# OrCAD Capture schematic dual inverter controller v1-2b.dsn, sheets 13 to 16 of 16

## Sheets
13 Temperature Sense: size A; title: Controller
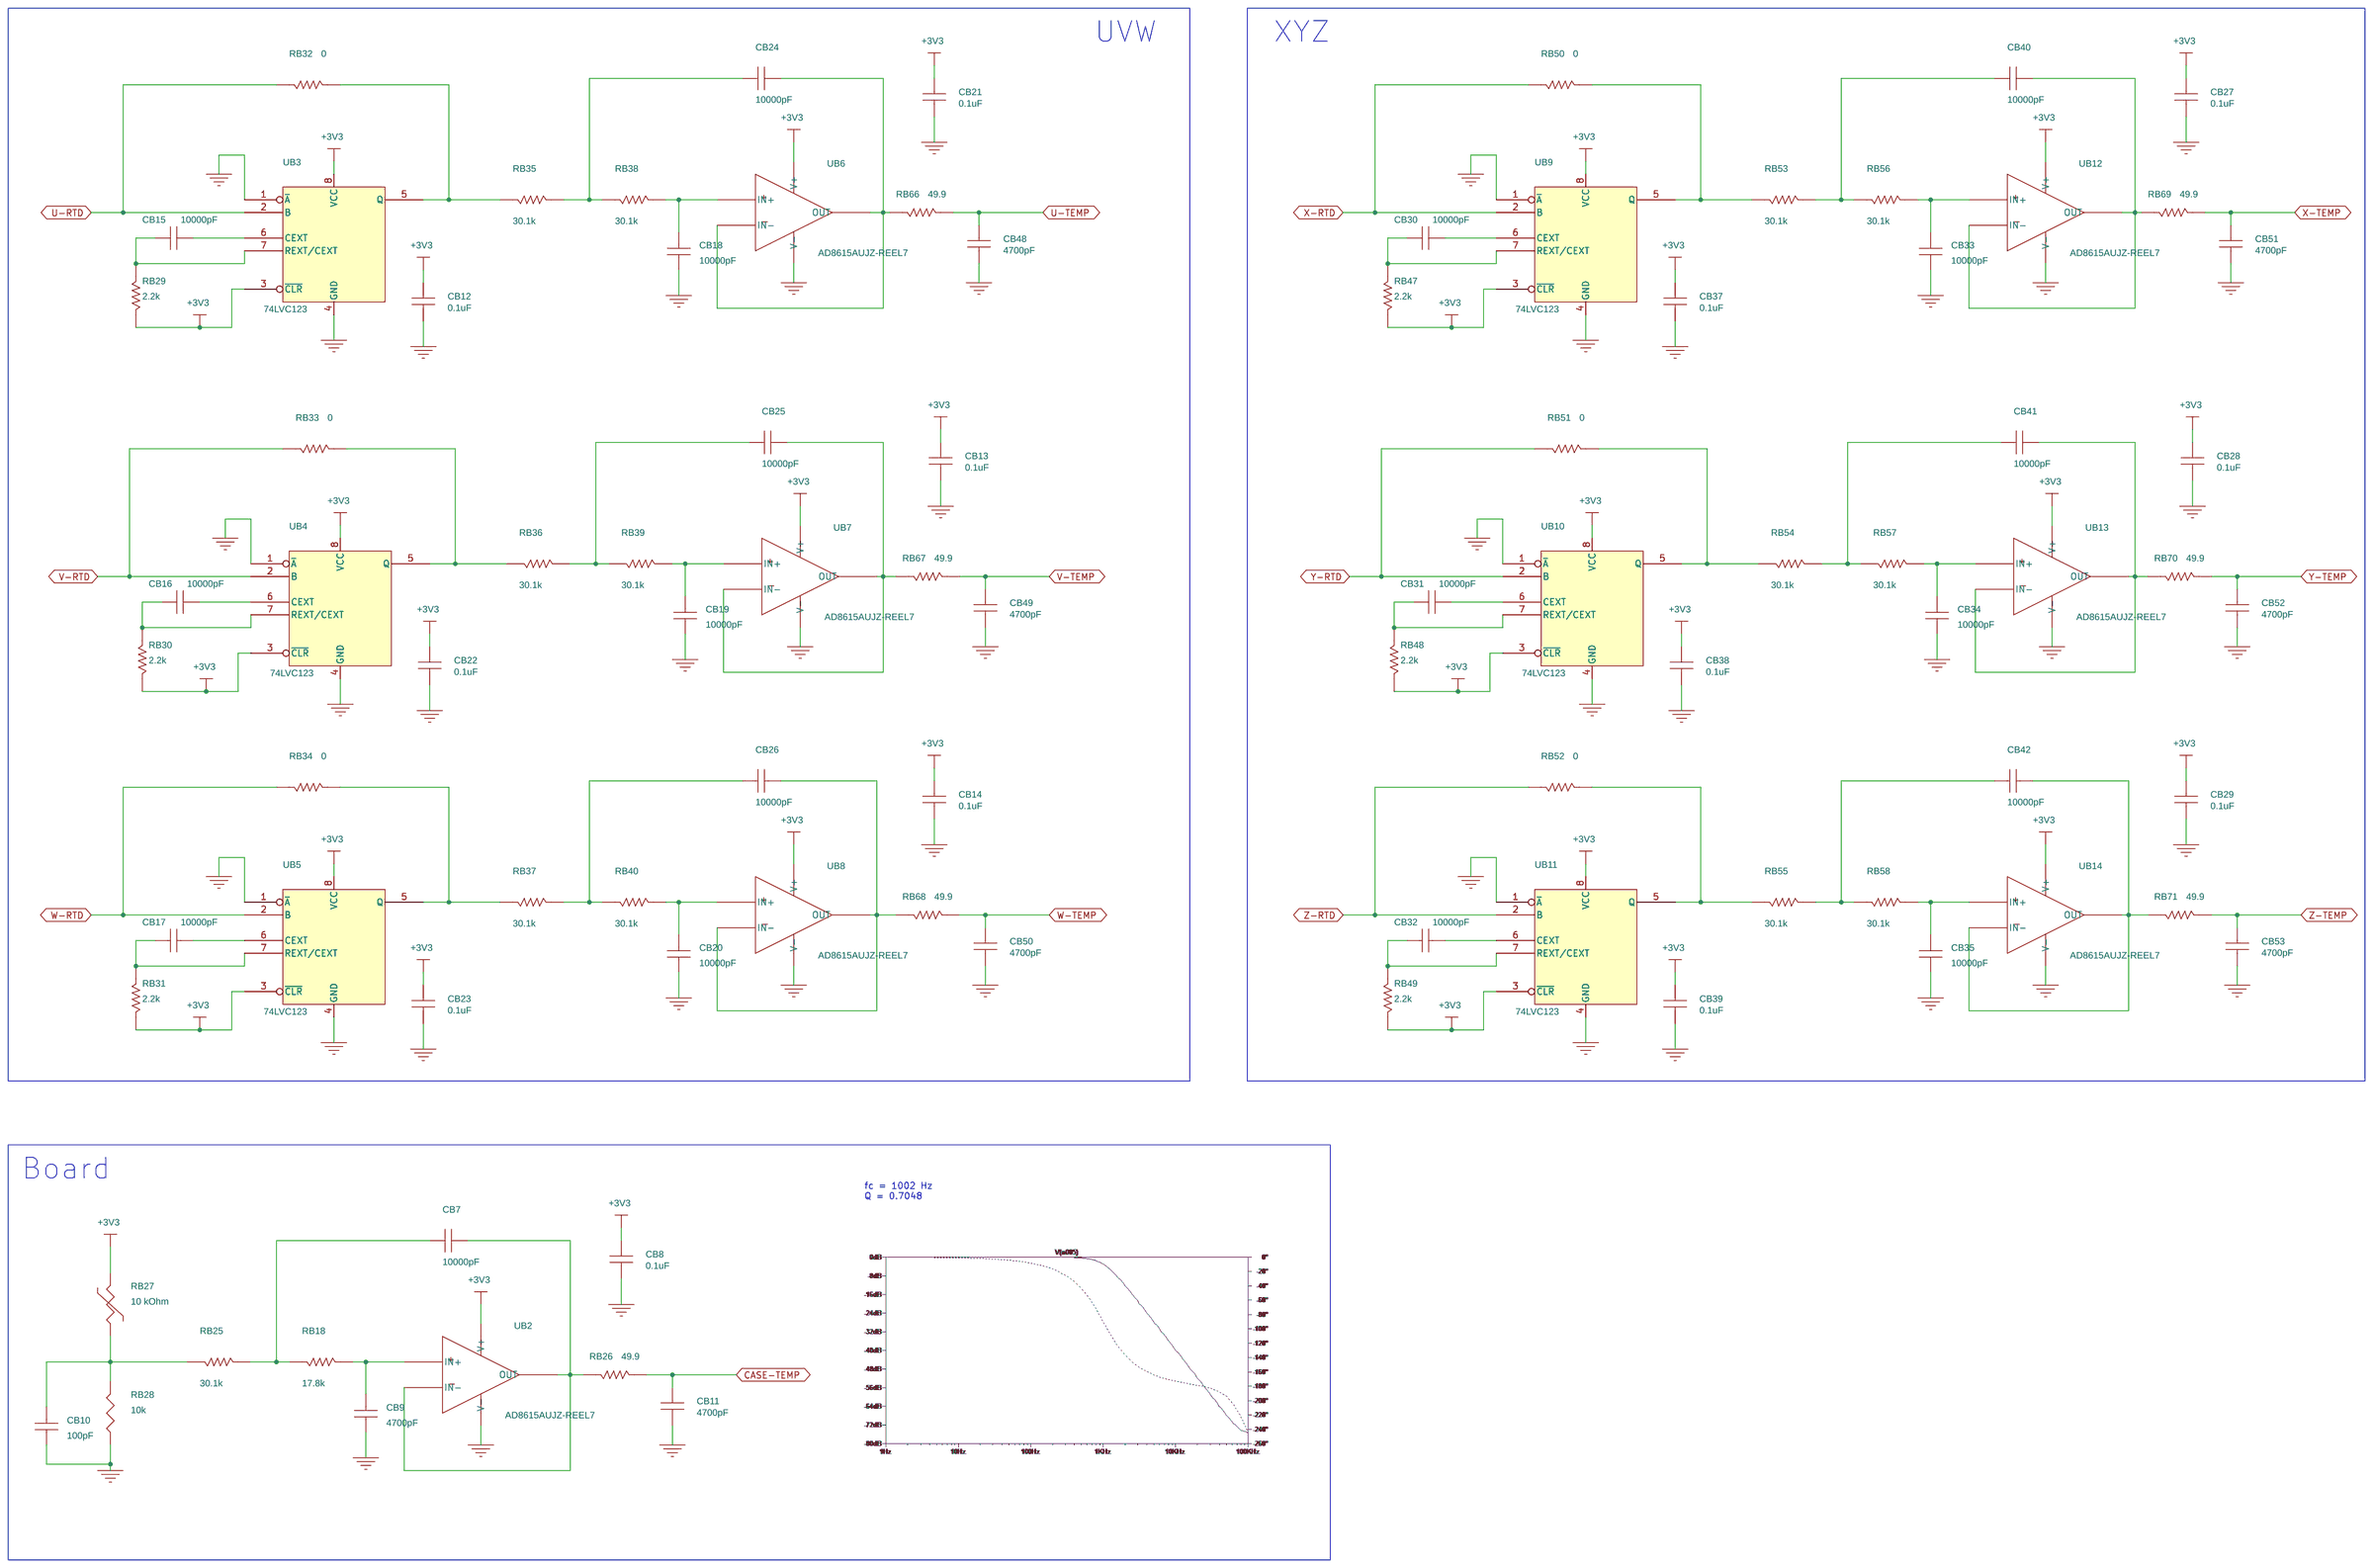
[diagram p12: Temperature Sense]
14 Voltage Sense UVW: size A; title: Controller
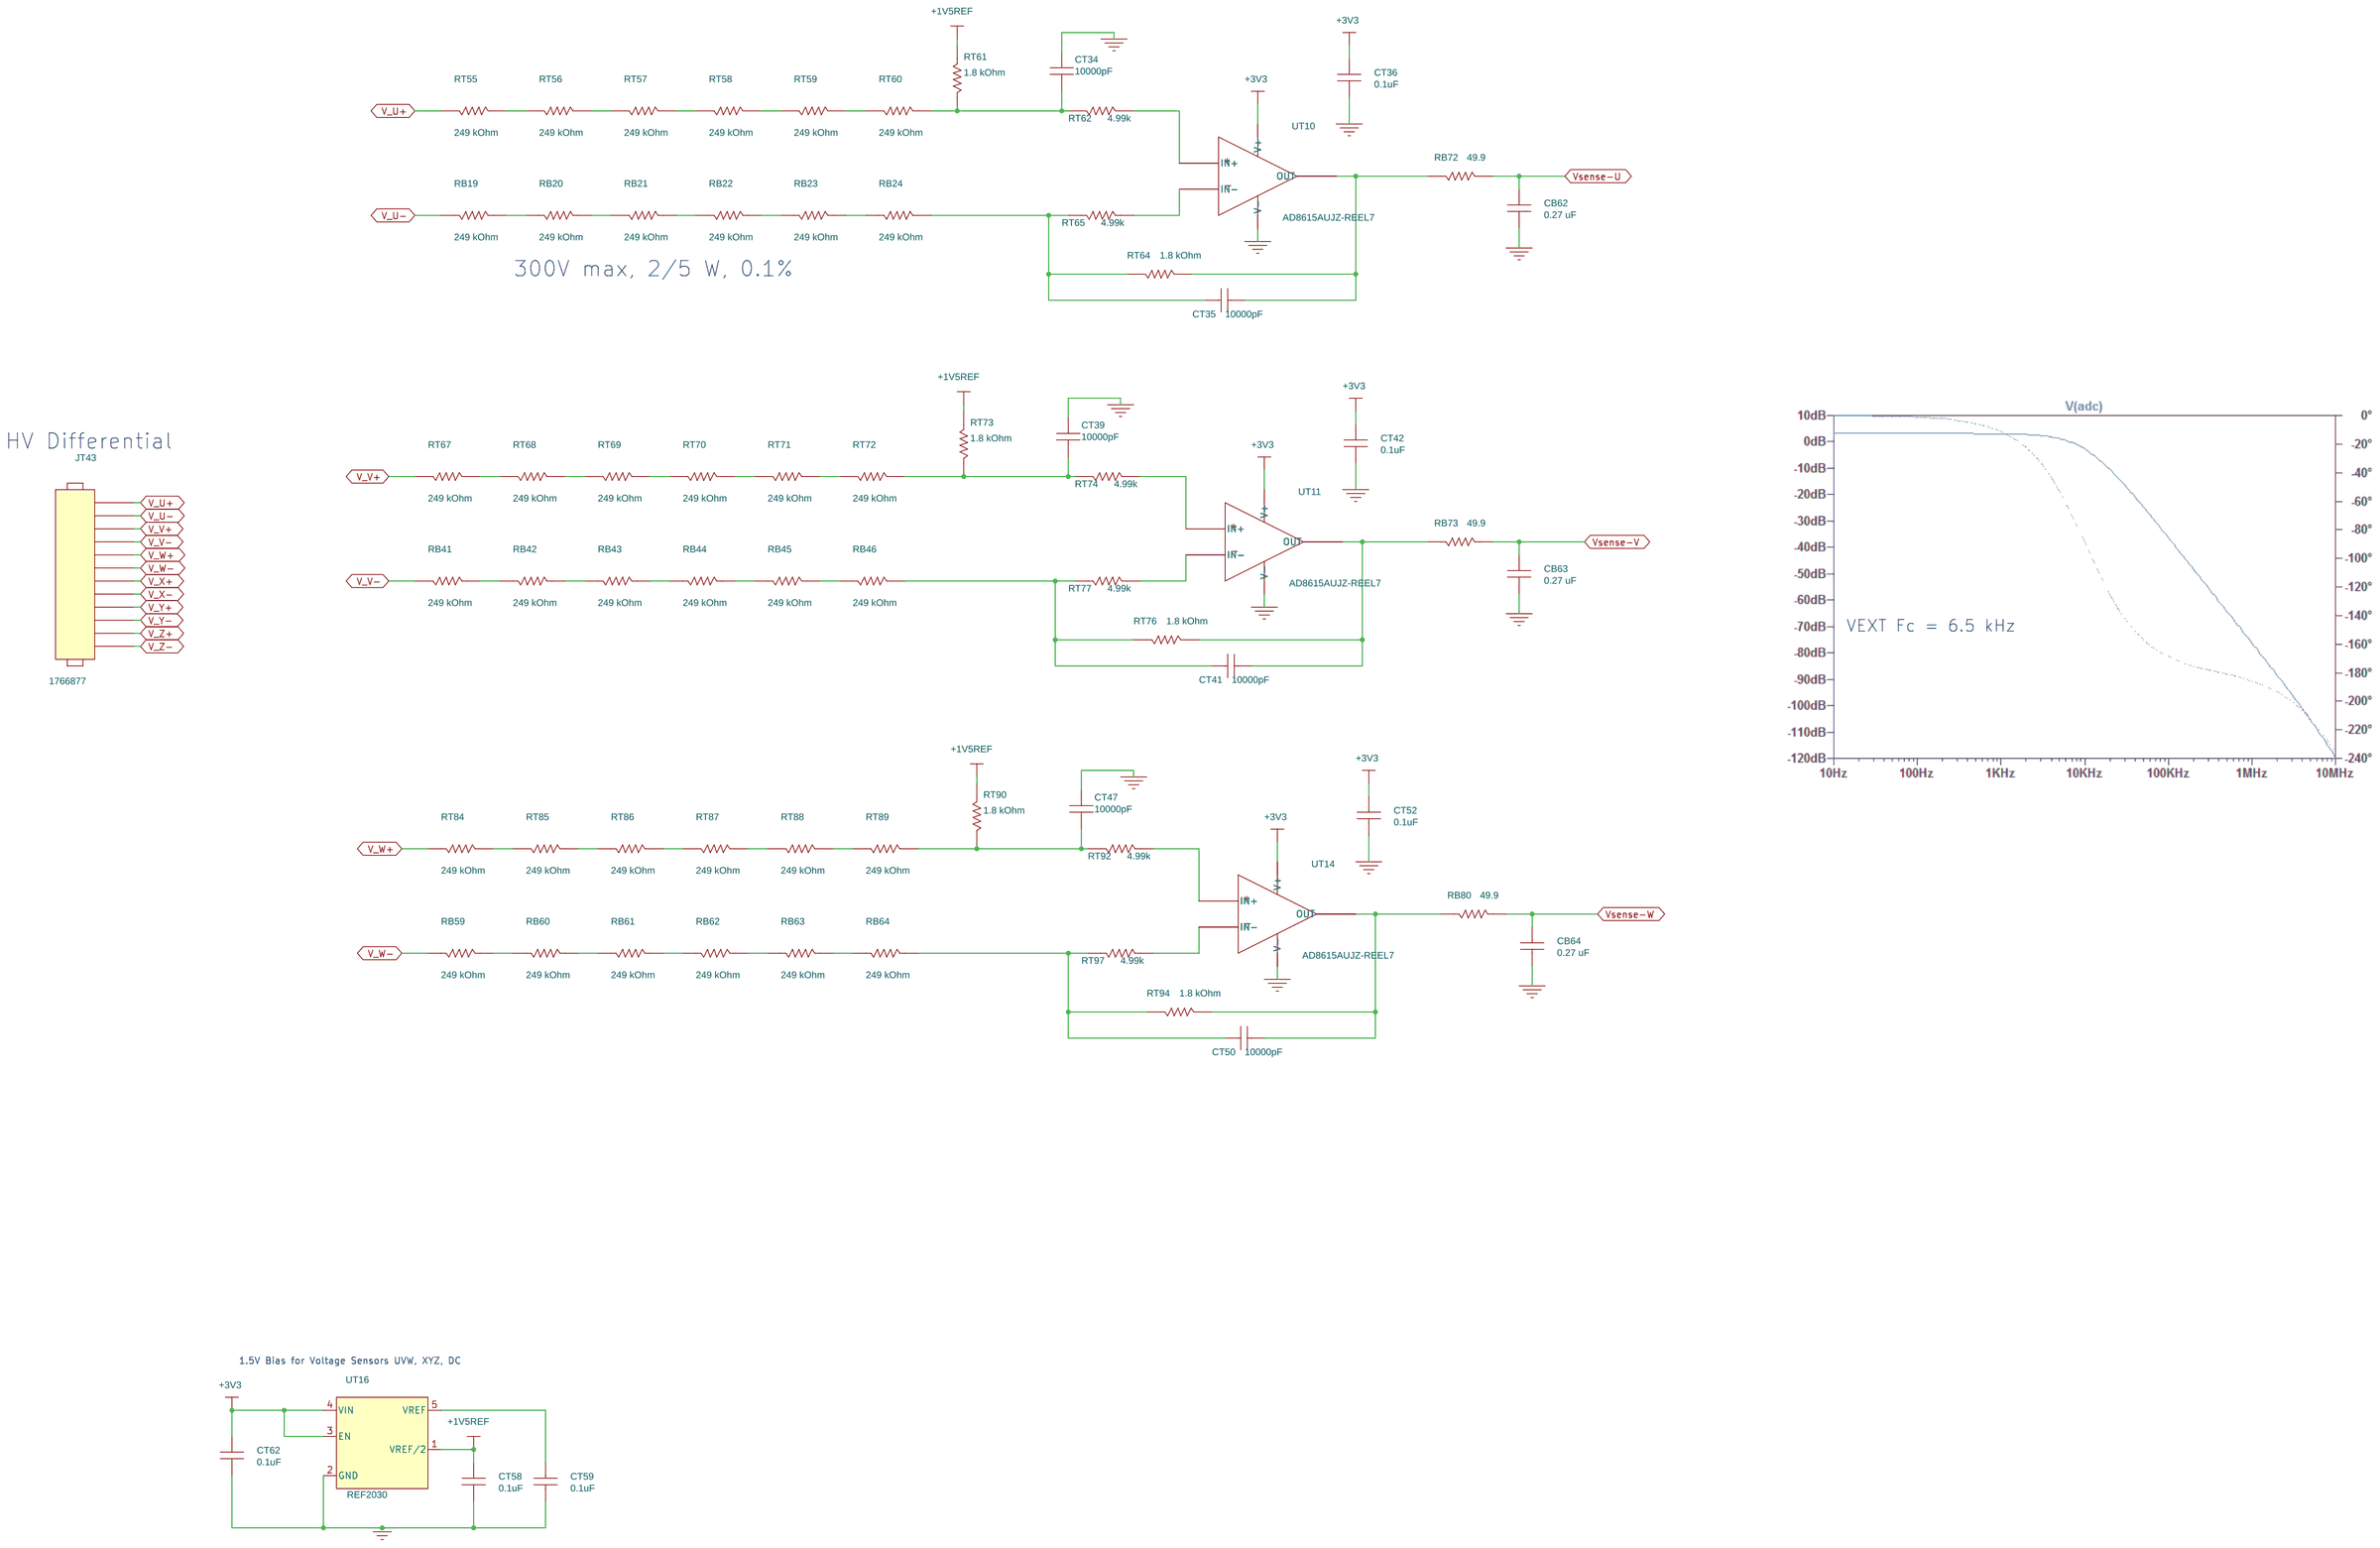
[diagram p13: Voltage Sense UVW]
15 Voltage Sense VDC: size A; title: Controller
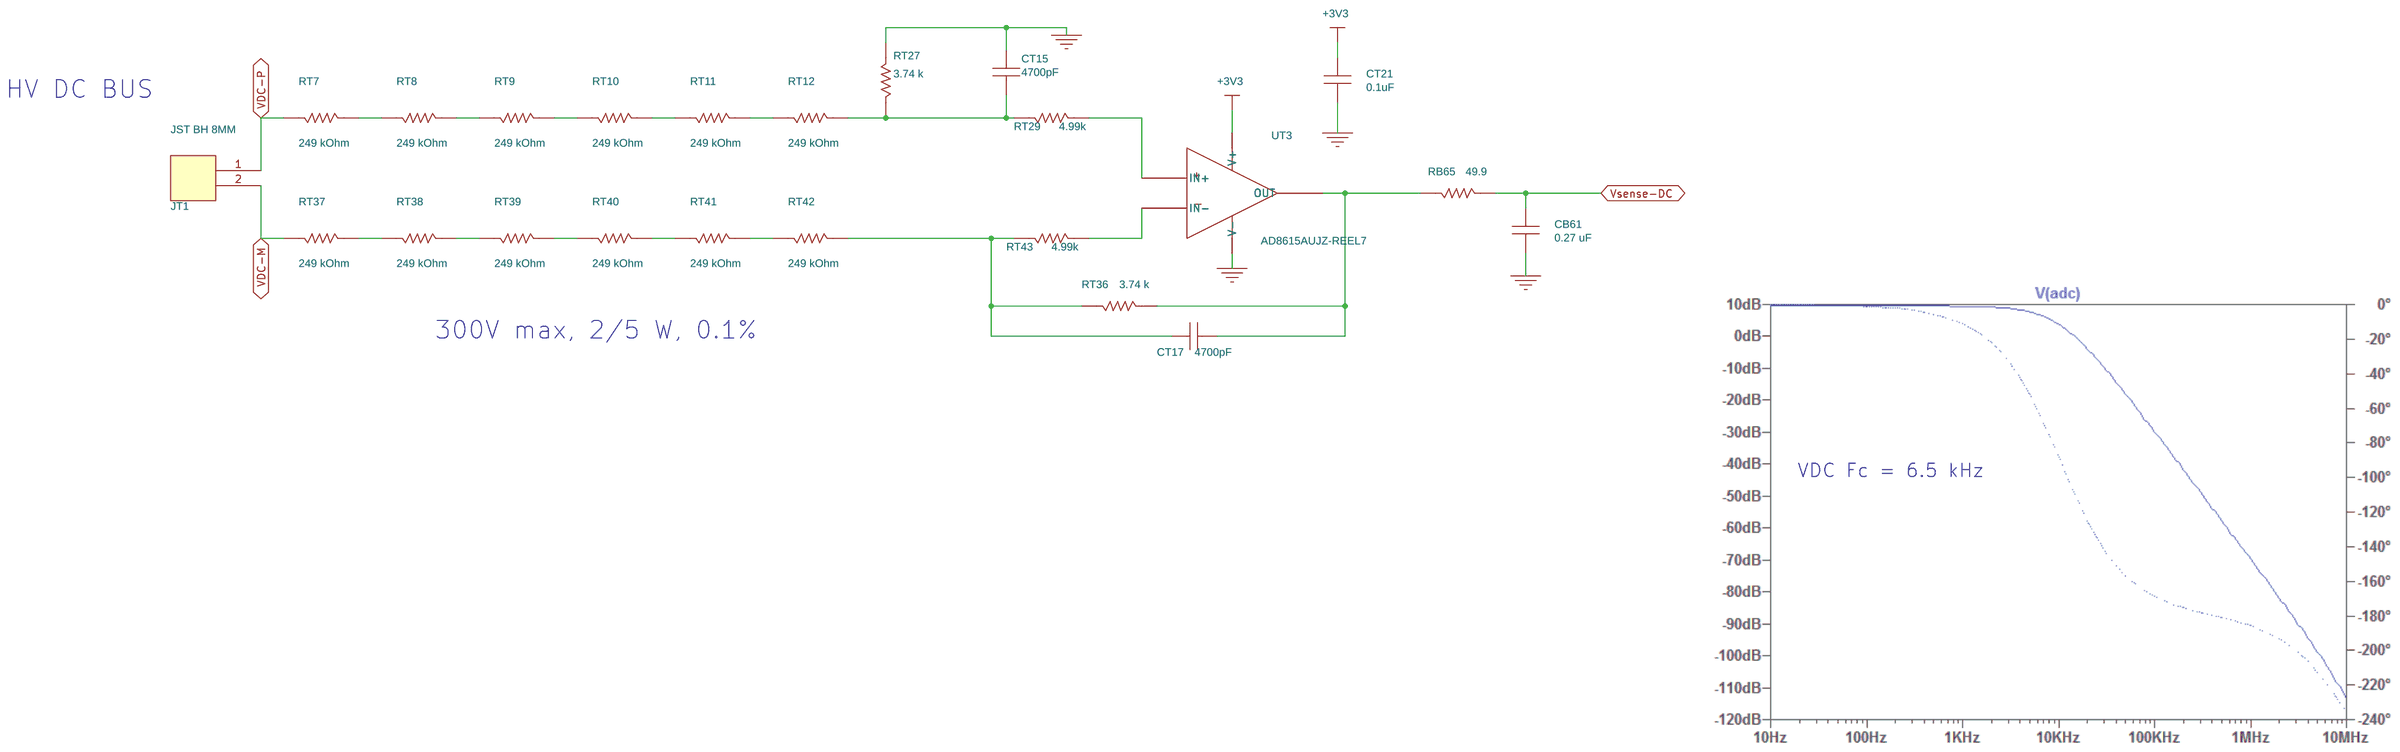
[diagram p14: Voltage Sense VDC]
16 Voltage Sense XYZ: size A; title: Controller
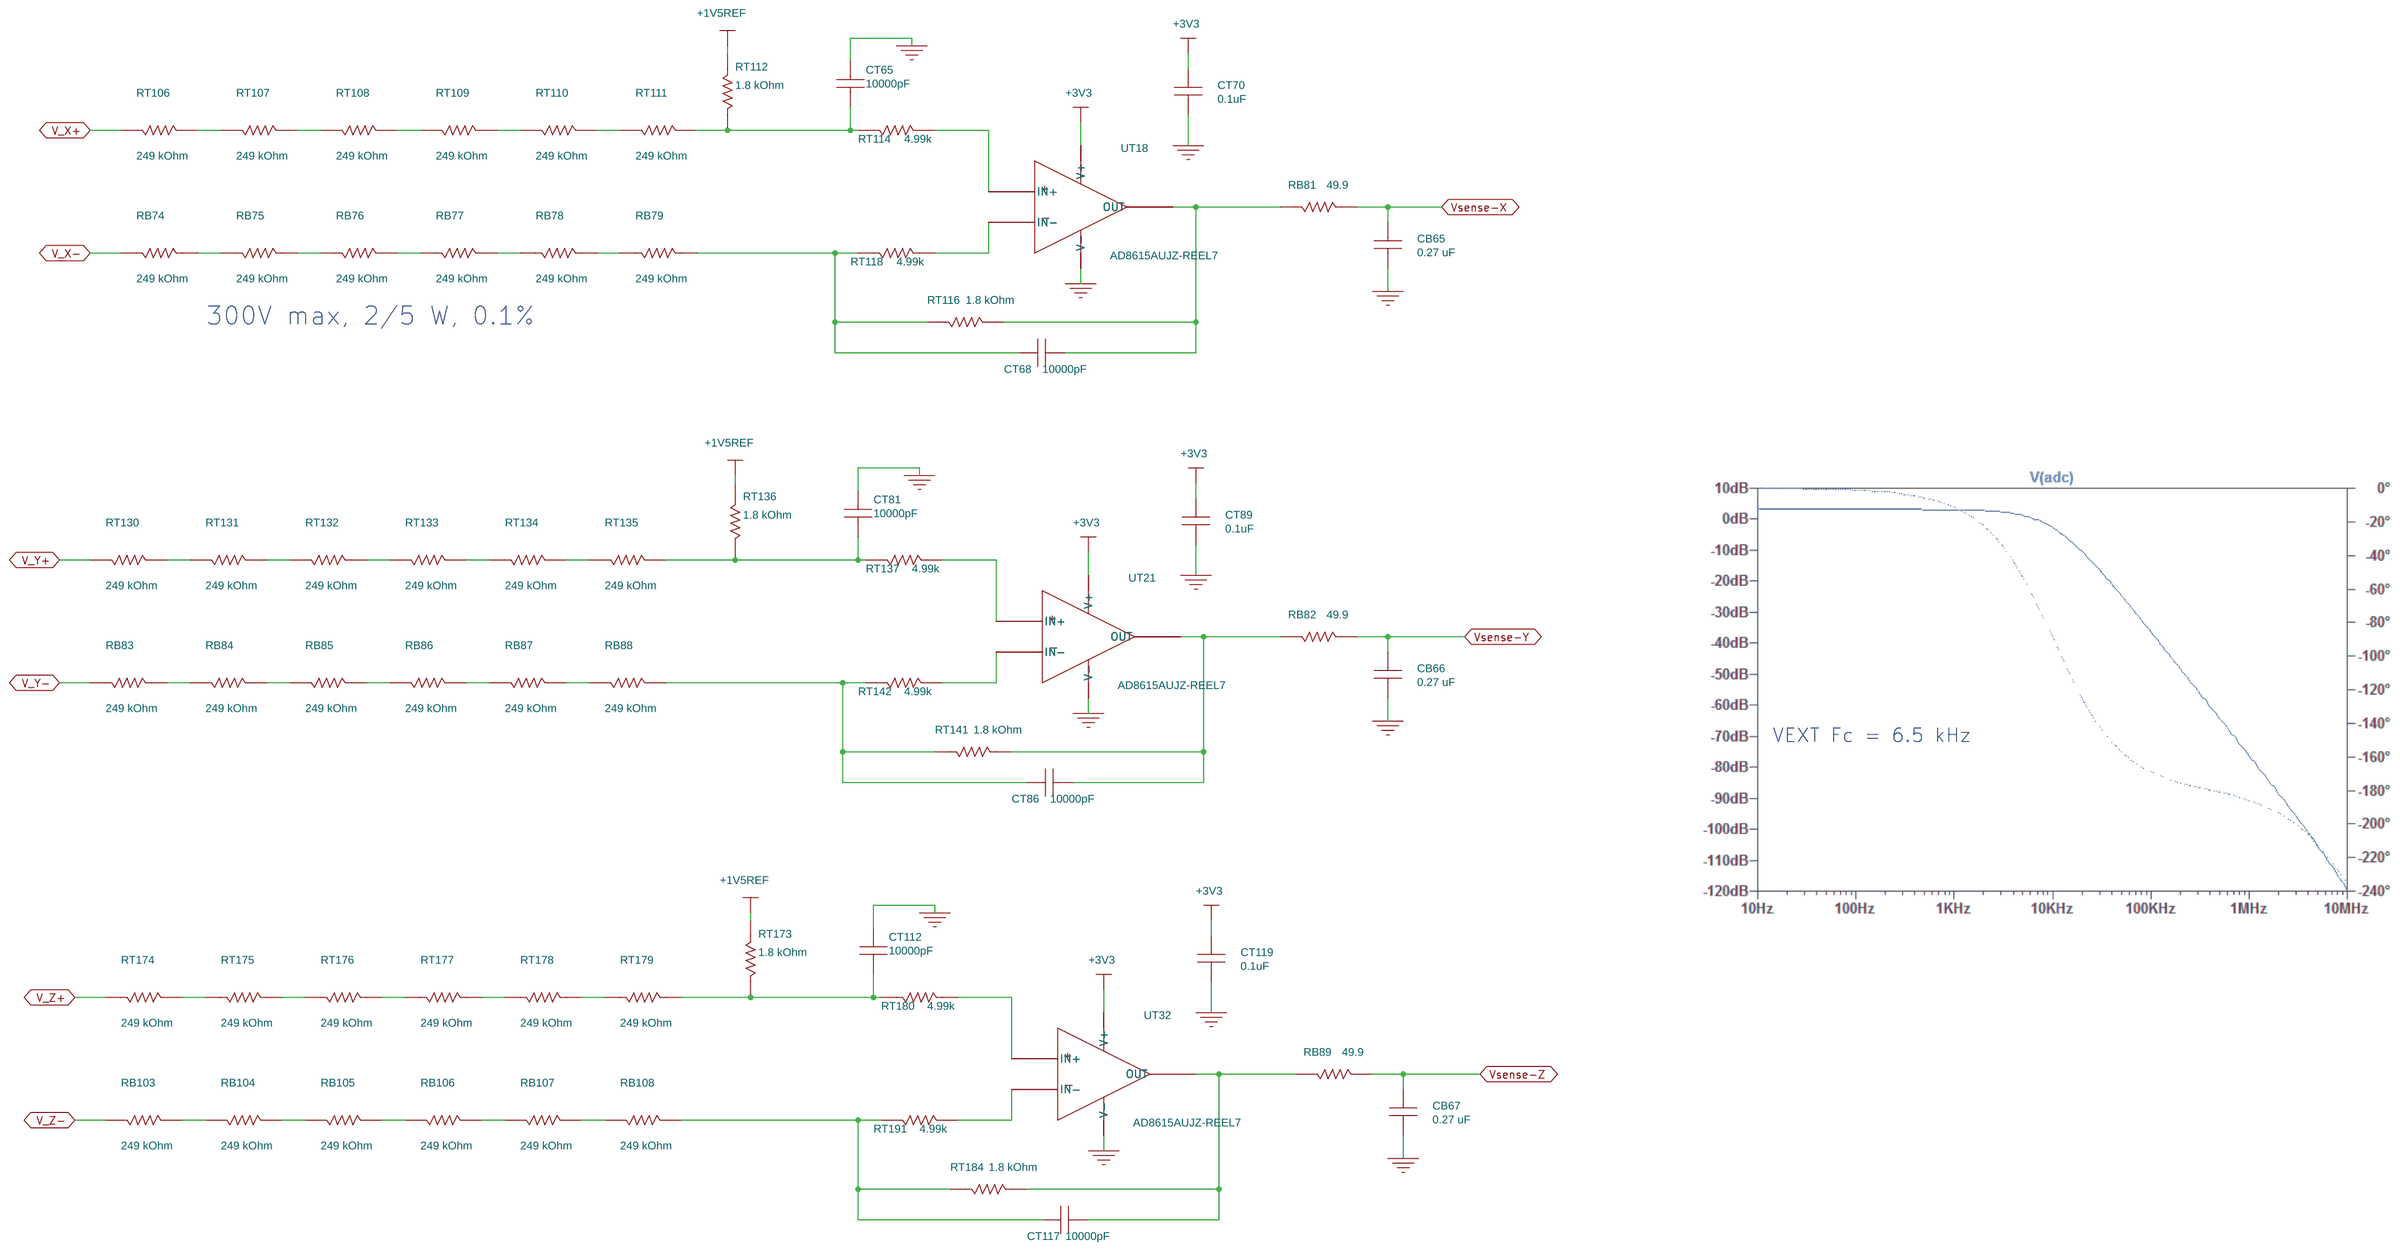
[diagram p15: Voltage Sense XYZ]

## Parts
sheet Temperature Sense
CB7  10000pF  [CAPC1608X90N]
CB8  0.1uF  [CAPC1608X87N]
CB9  4700pF  [CAPC1608X90N]
CB10  100pF  [CAPC1608X90N]
CB11  4700pF  [CAPC1608X87N]
CB12  0.1uF  [CAPC1608X87N]
CB13  0.1uF  [CAPC1608X87N]
CB14  0.1uF  [CAPC1608X87N]
CB15  10000pF  [CAPC1608X90N]
CB16  10000pF  [CAPC1608X90N]
CB17  10000pF  [CAPC1608X90N]
CB18  10000pF  [CAPC1608X90N]
CB19  10000pF  [CAPC1608X90N]
CB20  10000pF  [CAPC1608X90N]
CB21  0.1uF  [CAPC1608X87N]
CB22  0.1uF  [CAPC1608X87N]
CB23  0.1uF  [CAPC1608X87N]
CB24  10000pF  [CAPC1608X90N]
CB25  10000pF  [CAPC1608X90N]
CB26  10000pF  [CAPC1608X90N]
CB27  0.1uF  [CAPC1608X87N]
CB28  0.1uF  [CAPC1608X87N]
CB29  0.1uF  [CAPC1608X87N]
CB30  10000pF  [CAPC1608X90N]
CB31  10000pF  [CAPC1608X90N]
CB32  10000pF  [CAPC1608X90N]
CB33  10000pF  [CAPC1608X90N]
CB34  10000pF  [CAPC1608X90N]
CB35  10000pF  [CAPC1608X90N]
CB37  0.1uF  [CAPC1608X87N]
CB38  0.1uF  [CAPC1608X87N]
CB39  0.1uF  [CAPC1608X87N]
CB40  10000pF  [CAPC1608X90N]
CB41  10000pF  [CAPC1608X90N]
CB42  10000pF  [CAPC1608X90N]
CB48  4700pF  [CAPC1608X87N]
CB49  4700pF  [CAPC1608X87N]
CB50  4700pF  [CAPC1608X87N]
CB51  4700pF  [CAPC1608X87N]
CB52  4700pF  [CAPC1608X87N]
CB53  4700pF  [CAPC1608X87N]
RB18  17.8k  [RESC1608X55N]
RB25  30.1k  [RESC1608X55N]
RB26  49.9  [RESC1608X55N]
RB27  10 kOhm  [RESC2012X60N]
RB28  10k  [RESC1608X65N]
RB29  2.2k  [RESC1608X55N]
RB30  2.2k  [RESC1608X55N]
RB31  2.2k  [RESC1608X55N]
RB32  0  [RESC2012X70N]
RB33  0  [RESC2012X70N]
RB34  0  [RESC2012X70N]
RB35  30.1k  [RESC1608X55N]
RB36  30.1k  [RESC1608X55N]
RB37  30.1k  [RESC1608X55N]
RB38  30.1k  [RESC1608X55N]
RB39  30.1k  [RESC1608X55N]
RB40  30.1k  [RESC1608X55N]
RB47  2.2k  [RESC1608X55N]
RB48  2.2k  [RESC1608X55N]
RB49  2.2k  [RESC1608X55N]
RB50  0  [RESC2012X70N]
RB51  0  [RESC2012X70N]
RB52  0  [RESC2012X70N]
RB53  30.1k  [RESC1608X55N]
RB54  30.1k  [RESC1608X55N]
RB55  30.1k  [RESC1608X55N]
RB56  30.1k  [RESC1608X55N]
RB57  30.1k  [RESC1608X55N]
RB58  30.1k  [RESC1608X55N]
RB66  49.9  [RESC1608X55N]
RB67  49.9  [RESC1608X55N]
RB68  49.9  [RESC1608X55N]
RB69  49.9  [RESC1608X55N]
RB70  49.9  [RESC1608X55N]
RB71  49.9  [RESC1608X55N]
UB2  AD8615AUJZ-REEL7  [sot23-5_0_95x2_70p_h1_22]
UB3  74LVC123  [VFSOP-8]
UB4  74LVC123  [VFSOP-8]
UB5  74LVC123  [VFSOP-8]
UB6  AD8615AUJZ-REEL7  [sot23-5_0_95x2_70p_h1_22]
UB7  AD8615AUJZ-REEL7  [sot23-5_0_95x2_70p_h1_22]
UB8  AD8615AUJZ-REEL7  [sot23-5_0_95x2_70p_h1_22]
UB9  74LVC123  [VFSOP-8]
UB10  74LVC123  [VFSOP-8]
UB11  74LVC123  [VFSOP-8]
UB12  AD8615AUJZ-REEL7  [sot23-5_0_95x2_70p_h1_22]
UB13  AD8615AUJZ-REEL7  [sot23-5_0_95x2_70p_h1_22]
UB14  AD8615AUJZ-REEL7  [sot23-5_0_95x2_70p_h1_22]
sheet Voltage Sense UVW
CB62  0.27 uF  [CAPC1608X90N]
CB63  0.27 uF  [CAPC1608X90N]
CB64  0.27 uF  [CAPC1608X90N]
CT34  10000pF  [CAPC1608X90N]
CT35  10000pF  [CAPC1608X90N]
CT36  0.1uF  [CAPC1608X87N]
CT39  10000pF  [CAPC1608X90N]
CT41  10000pF  [CAPC1608X90N]
CT42  0.1uF  [CAPC1608X87N]
CT47  10000pF  [CAPC1608X90N]
CT50  10000pF  [CAPC1608X90N]
CT52  0.1uF  [CAPC1608X87N]
CT58  0.1uF  [CAPC1608X87N]
CT59  0.1uF  [CAPC1608X87N]
CT62  0.1uF  [CAPC1608X87N]
JT43  1766877  [Phoenix_1766877]
RB19  249 kOhm  [RESC3216X65N]
RB20  249 kOhm  [RESC3216X65N]
RB21  249 kOhm  [RESC3216X65N]
RB22  249 kOhm  [RESC3216X65N]
RB23  249 kOhm  [RESC3216X65N]
RB24  249 kOhm  [RESC3216X65N]
RB41  249 kOhm  [RESC3216X65N]
RB42  249 kOhm  [RESC3216X65N]
RB43  249 kOhm  [RESC3216X65N]
RB44  249 kOhm  [RESC3216X65N]
RB45  249 kOhm  [RESC3216X65N]
RB46  249 kOhm  [RESC3216X65N]
RB59  249 kOhm  [RESC3216X65N]
RB60  249 kOhm  [RESC3216X65N]
RB61  249 kOhm  [RESC3216X65N]
RB62  249 kOhm  [RESC3216X65N]
RB63  249 kOhm  [RESC3216X65N]
RB64  249 kOhm  [RESC3216X65N]
RB72  49.9  [RESC1608X55N]
RB73  49.9  [RESC1608X55N]
RB80  49.9  [RESC1608X55N]
RT55  249 kOhm  [RESC3216X65N]
RT56  249 kOhm  [RESC3216X65N]
RT57  249 kOhm  [RESC3216X65N]
RT58  249 kOhm  [RESC3216X65N]
RT59  249 kOhm  [RESC3216X65N]
RT60  249 kOhm  [RESC3216X65N]
RT61  1.8 kOhm  [RESC1608X55N]
RT62  4.99k  [RESC1608X55N]
RT64  1.8 kOhm  [RESC1608X55N]
RT65  4.99k  [RESC1608X55N]
RT67  249 kOhm  [RESC3216X65N]
RT68  249 kOhm  [RESC3216X65N]
RT69  249 kOhm  [RESC3216X65N]
RT70  249 kOhm  [RESC3216X65N]
RT71  249 kOhm  [RESC3216X65N]
RT72  249 kOhm  [RESC3216X65N]
RT73  1.8 kOhm  [RESC1608X55N]
RT74  4.99k  [RESC1608X55N]
RT76  1.8 kOhm  [RESC1608X55N]
RT77  4.99k  [RESC1608X55N]
RT84  249 kOhm  [RESC3216X65N]
RT85  249 kOhm  [RESC3216X65N]
RT86  249 kOhm  [RESC3216X65N]
RT87  249 kOhm  [RESC3216X65N]
RT88  249 kOhm  [RESC3216X65N]
RT89  249 kOhm  [RESC3216X65N]
RT90  1.8 kOhm  [RESC1608X55N]
RT92  4.99k  [RESC1608X55N]
RT94  1.8 kOhm  [RESC1608X55N]
RT97  4.99k  [RESC1608X55N]
UT10  AD8615AUJZ-REEL7  [sot23-5_0_95x2_70p_h1_22]
UT11  AD8615AUJZ-REEL7  [sot23-5_0_95x2_70p_h1_22]
UT14  AD8615AUJZ-REEL7  [sot23-5_0_95x2_70p_h1_22]
UT16  REF2030  [SOT23-5_0_95X2_70P_H1_45]
sheet Voltage Sense VDC
CB61  0.27 uF  [CAPC1608X90N]
CT15  4700pF  [CAPC1608X90N]
CT17  4700pF  [CAPC1608X90N]
CT21  0.1uF  [CAPC1608X87N]
JT1  JST BH 8MM  [CON_JST-BHS-8MM-2PIN]
RB65  49.9  [RESC1608X55N]
RT7  249 kOhm  [RESC3216X65N]
RT8  249 kOhm  [RESC3216X65N]
RT9  249 kOhm  [RESC3216X65N]
RT10  249 kOhm  [RESC3216X65N]
RT11  249 kOhm  [RESC3216X65N]
RT12  249 kOhm  [RESC3216X65N]
RT27  3.74 k  [RESC1608X55N]
RT29  4.99k  [RESC1608X55N]
RT36  3.74 k  [RESC1608X55N]
RT37  249 kOhm  [RESC3216X65N]
RT38  249 kOhm  [RESC3216X65N]
RT39  249 kOhm  [RESC3216X65N]
RT40  249 kOhm  [RESC3216X65N]
RT41  249 kOhm  [RESC3216X65N]
RT42  249 kOhm  [RESC3216X65N]
RT43  4.99k  [RESC1608X55N]
UT3  AD8615AUJZ-REEL7  [sot23-5_0_95x2_70p_h1_22]
sheet Voltage Sense XYZ
CB65  0.27 uF  [CAPC1608X90N]
CB66  0.27 uF  [CAPC1608X90N]
CB67  0.27 uF  [CAPC1608X90N]
CT65  10000pF  [CAPC1608X90N]
CT68  10000pF  [CAPC1608X90N]
CT70  0.1uF  [CAPC1608X87N]
CT81  10000pF  [CAPC1608X90N]
CT86  10000pF  [CAPC1608X90N]
CT89  0.1uF  [CAPC1608X87N]
CT112  10000pF  [CAPC1608X90N]
CT117  10000pF  [CAPC1608X90N]
CT119  0.1uF  [CAPC1608X87N]
RB74  249 kOhm  [RESC3216X65N]
RB75  249 kOhm  [RESC3216X65N]
RB76  249 kOhm  [RESC3216X65N]
RB77  249 kOhm  [RESC3216X65N]
RB78  249 kOhm  [RESC3216X65N]
RB79  249 kOhm  [RESC3216X65N]
RB81  49.9  [RESC1608X55N]
RB82  49.9  [RESC1608X55N]
RB83  249 kOhm  [RESC3216X65N]
RB84  249 kOhm  [RESC3216X65N]
RB85  249 kOhm  [RESC3216X65N]
RB86  249 kOhm  [RESC3216X65N]
RB87  249 kOhm  [RESC3216X65N]
RB88  249 kOhm  [RESC3216X65N]
RB89  49.9  [RESC1608X55N]
RB103  249 kOhm  [RESC3216X65N]
RB104  249 kOhm  [RESC3216X65N]
RB105  249 kOhm  [RESC3216X65N]
RB106  249 kOhm  [RESC3216X65N]
RB107  249 kOhm  [RESC3216X65N]
RB108  249 kOhm  [RESC3216X65N]
RT106  249 kOhm  [RESC3216X65N]
RT107  249 kOhm  [RESC3216X65N]
RT108  249 kOhm  [RESC3216X65N]
RT109  249 kOhm  [RESC3216X65N]
RT110  249 kOhm  [RESC3216X65N]
RT111  249 kOhm  [RESC3216X65N]
RT112  1.8 kOhm  [RESC1608X55N]
RT114  4.99k  [RESC1608X55N]
RT116  1.8 kOhm  [RESC1608X55N]
RT118  4.99k  [RESC1608X55N]
RT130  249 kOhm  [RESC3216X65N]
RT131  249 kOhm  [RESC3216X65N]
RT132  249 kOhm  [RESC3216X65N]
RT133  249 kOhm  [RESC3216X65N]
RT134  249 kOhm  [RESC3216X65N]
RT135  249 kOhm  [RESC3216X65N]
RT136  1.8 kOhm  [RESC1608X55N]
RT137  4.99k  [RESC1608X55N]
RT141  1.8 kOhm  [RESC1608X55N]
RT142  4.99k  [RESC1608X55N]
RT173  1.8 kOhm  [RESC1608X55N]
RT174  249 kOhm  [RESC3216X65N]
RT175  249 kOhm  [RESC3216X65N]
RT176  249 kOhm  [RESC3216X65N]
RT177  249 kOhm  [RESC3216X65N]
RT178  249 kOhm  [RESC3216X65N]
RT179  249 kOhm  [RESC3216X65N]
RT180  4.99k  [RESC1608X55N]
RT184  1.8 kOhm  [RESC1608X55N]
RT191  4.99k  [RESC1608X55N]
UT18  AD8615AUJZ-REEL7  [sot23-5_0_95x2_70p_h1_22]
UT21  AD8615AUJZ-REEL7  [sot23-5_0_95x2_70p_h1_22]
UT32  AD8615AUJZ-REEL7  [sot23-5_0_95x2_70p_h1_22]

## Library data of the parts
CB7 CB15-CB20 CB24-CB26 CB30-CB35 CB40-CB42 CT34 CT35 CT39 CT41 CT47 CT50 CT65 CT68 CT81 CT86 CT112 CT117 = CAP: CAP CER 10000PF 25V 10% X7R 0603; CLASS: DISCRETE; Company Part Status: New; Dielectric Type: Capacitors; Manufacturer: Samsung Electro-Mechanics America, Inc.; Manufacturer PN: CL10B103KA8NNNC; PART_NUMBER: TMP-566; Package Size: 0603 (1608 Metric); Rated Voltage: 25V; Temperature Coefficient: X7R; Tolerance: 10%
CB8 CB12-CB14 CB21-CB23 CB27-CB29 CB37-CB39 CT21 CT36 CT42 CT52 CT58 CT59 CT62 CT70 CT89 CT119 = CAP: CAP CER 0.1UF 25V X7R 0603; CLASS: DISCRETE; Company Part Status: New; Dielectric Type: Capacitors; Manufacturer: Kemet; Manufacturer PN: C0603C104K3RACTU; PART_NUMBER: TMP-847; Package Size: 0603 (1608 Metric); Rated Voltage: 25V; Temperature Coefficient: X7R; Tolerance: 10%
CB9 CT15 CT17 = CAP: CAP CER 4700PF 25V X7R 0603; CLASS: DISCRETE; Dielectric Type: Capacitors; Manufacturer: Murata Electronics North America; Manufacturer PN: GCM188R71E472KA37D; PART_NUMBER: TMP-889; Package Size: 0603 (1608 Metric); Temperature Coefficient: X7R; Tolerance: 10%
CB10 = CAP: CAP CER 100PF 50V 5% NP0 0603; CLASS: DISCRETE; Company Part Status: New; Dielectric Type: Capacitors; Manufacturer: Samsung Electro-Mechanics America, Inc; Manufacturer PN: CL10C101JB8NNNC; PART_NUMBER: TMP-455; Package Size: 0603 (1608 Metric); Rated Voltage: 50V; Temperature Coefficient: C0G, NP0; Tolerance: 5%
CB11 CB48-CB53 = CAP: CAP CER 4700PF 25V X7R 0603; CLASS: DISCRETE; Company Part Status: New; Dielectric Type: Capacitors; Manufacturer: Murata Electronics North America; Manufacturer PN: GCM188R71E472KA37D; PART_NUMBER: TMP-889; Package Size: 0603 (1608 Metric); Rated Voltage: 25V; Temperature Coefficient: X7R; Tolerance: 10%
RB18 = RES: RES SMD 17.8K OHM 1% 1/10W 0603; CLASS: DISCRETE; Company Part Status: Released; Manufacturer: Panasonic Electronic Components; Manufacturer PN: ERJ-3EKF1782V; PART_NUMBER: TMP-995; Package Size: 0603 (1608 Metric); Rated Power: 0.1W, 1/10W; Temperature Coefficient: 100ppm/C; Tolerance: 1%
RB25 RB35-RB40 RB53-RB58 = RES: RES SMD 30.1K OHM 1% 1/10W 0603; CLASS: DISCRETE; Company Part Status: New; Manufacturer: Panasonic Electronic Components; Manufacturer PN: ERJ-3EKF3012V; PART_NUMBER: TMP-962; Package Size: 0603 (1608 Metric); Rated Power: 0.1W, 1/10W; Temperature Coefficient: 100ppm/C; Tolerance: 1%
RB26 RB65-RB73 RB80-RB82 RB89 = RES: RES SMD 49.9 OHM 1% 1/10W 0603; CLASS: DISCRETE; Company Part Status: New; Manufacturer: Panasonic Electronic Components; Manufacturer PN: ERJ-3EKF49R9V; PART_NUMBER: TMP-1252; Package Size: 0603 (1608 Metric); Rated Power: 0.1W, 1/10W; Temperature Coefficient: 100ppm/C; Tolerance: 1%
RB27 = PTC: THERMISTOR NTC 10KOHM 3900K 0805; CLASS: DISCRETE; Company Part Status: New; Manufacturer: Murata Electronics North America; Manufacturer PN: NCP21XV103J03RA; PART_NUMBER: TMP-1511; Package Size: 0805 (2012 Metric); Rated Power: 200mW; Temperature Coefficient: 3900K; Tolerance: 5%
RB28 = R: RES SMD 10K OHM 1% 1/10W 0603; CLASS: DISCRETE; Company Part Status: New; Manufacturer: Rohm Semiconductor; Manufacturer PN: MCR03ERTF1002; PART_NUMBER: TMP-380; Package Size: 0603 (1608 Metric); Rated Power: 0.1W, 1/10W; Temperature Coefficient: 100ppm/C; Tolerance: 1%
RB29-RB31 RB47-RB49 = RES: RES SMD 2.2K OHM 1% 1/10W 0603; CLASS: DISCRETE; Company Part Status: New; Manufacturer: Yageo; Manufacturer PN: RC0603FR-072K2L; PART_NUMBER: TMP-1308; Package Size: 0603 (1608 Metric); Rated Power: 0.1W, 1/10W; Temperature Coefficient: 100ppm/C; Tolerance: 1%
RB32-RB34 RB50-RB52 = RES_0: RES SMD 0 OHM JUMPER 1/8W 0805; CLASS: DISCRETE; Company Part Status: Released; Manufacturer: Samsung Electro-Mechanics; Manufacturer PN: RC2012J000CS; PART_NUMBER: TMP-1398; Package Size: 0805 (2012 Metric); Rated Power: 0.125W, 1/8W; Tolerance: Jumper
UB2 UB6-UB8 UB12-UB14 UT3 UT10 UT11 UT14 UT18 UT21 UT32 = AD8615: IC OPAMP GP 24MHZ RRO TSOT23-5; CLASS: IC; Company Part Status: New; Manufacturer: Analog Devices Inc.; PART_NUMBER: TMP-1499; Package Size: SOT-23-5 Thin, TSOT-23-5; Supply Voltage: 2.7 V - 5.5 V, 1.35 V - 2.75 V
UB3-UB5 UB9-UB11 = 74LVC123: IC SNGLE MONO MULTIVBTOR US8; CLASS: IC; Company Part Status: New; Manufacturer: Texas Instruments; Manufacturer PN: SN74LVC1G123DCUR; PART_NUMBER: TMP-1593; Package Size: 8-VFSOP (0.091", 2.30mm Width); Supply Voltage: 1.65V ~ 5.5V
CB61-CB67 = CAP: CAP CER 0.27UF 16V X7R 0603; CLASS: DISCRETE; Company Part Status: New; Dielectric Type: Capacitors; Manufacturer: Murata Electronics North America; Manufacturer PN: GCM188R71C274KA37D; PART_NUMBER: TMP-1544; Package Size: 0603 (1608 Metric); Rated Voltage: 16V; Temperature Coefficient: X7R; Tolerance: 10%
JT43 = 12_HEADER: TERM BLOCK HDR 12POS VERT 7.62MM; CLASS: IO; Company Part Status: New; Contact Voltage: 630V; Manufacturer: Phoenix Contact; PART_NUMBER: TMP-1730
RB19-RB24 RB41-RB46 RB59-RB64 RB74-RB79 RB83-RB88 RB103-RB108 RT7-RT12 RT37-RT42 RT55-RT60 RT67-RT72 RT84-RT89 RT106-RT111 RT130-RT135 RT174-RT179 = RES: RES 249K OHM 0.1% 2/5W 1206; CLASS: DISCRETE; Company Part Status: New; Manufacturer: Vishay Dale; Manufacturer PN: TNPW1206249KBEEA; PART_NUMBER: TMP-1522; Package Size: 1206 (3216 Metric); Rated Power: 0.4W, 2/5W; Temperature Coefficient: 25ppm/C; Tolerance: 0.1%
RT61 RT64 RT73 RT76 RT90 RT94 RT112 RT116 RT136 RT141 RT173 RT184 = RES: RES SMD 1.8K OHM 0.1% 1/5W 0603; CLASS: DISCRETE; Company Part Status: New; Manufacturer: Panasonic Electronic Components; Manufacturer PN: ERJ-PB3B1801V; PART_NUMBER: TMP-1523; Package Size: 0603 (1608 Metric); Rated Power: 0.2W, 1/5W; Temperature Coefficient: 50ppm/C; Tolerance: 0.1%
RT29 RT43 RT62 RT65 RT74 RT77 RT92 RT97 RT114 RT118 RT137 RT142 RT180 RT191 = RES: RES SMD 4.99K OHM 1% 1/10W 0603; CLASS: DISCRETE; Company Part Status: Released; Manufacturer: Yageo; Manufacturer PN: RC0603FR-074K99L; PART_NUMBER: TMP-871; Package Size: 0603 (1608 Metric); Rated Power: 0.1W, 1/10W; Temperature Coefficient: 100ppm/C; Tolerance: 1%
UT16 = REF2030: IC VREF SERIES 1.5V AND 3V 0.05% SOT23-5; CLASS: IC; Company Part Status: New; Manufacturer: Texas Instruments; Manufacturer PN: REF2030AIDDCT; PART_NUMBER: TMP-1708; Package Size: SOT-23-5 Thin, TSOT-23-5; Supply Voltage: 3 - 5.5 V
JT1 = CON2: CONN HEADER SMD R/A 2POS 8MM; CLASS: IO; Company Part Status: New; Contact Voltage: 600V; Manufacturer: JST Sales America Inc.; Manufacturer PN: SM02(8.0)B-BHS-1-TB(LF)(SN); PART_NUMBER: TMP-1676; STEP_MODEL: SM02_8_B-BHS-1-TB.STEP
RT27 RT36 = RES: RES SMD 3.74K OHM 0.1% 1/5W 0603; CLASS: DISCRETE; Company Part Status: New; Manufacturer: Panasonic Electronic Components; Manufacturer PN: ERJ-PB3B3741V; PART_NUMBER: TMP-1543; Package Size: 0603 (1608 Metric); Rated Power: 0.2W, 1/5W; Temperature Coefficient: 50ppm/C; Tolerance: 0.1%

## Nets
+1V5REF: CT58.1 RT61.1 RT73.1 RT90.1 RT112.1 RT136.1 RT173.1 UT16.1(VREF/2)
+3V3: CB8.1 CB12.1 CB13.1 CB14.1 CB21.1 CB22.1 CB23.1 CB27.1 CB28.1 CB29.1 CB37.1 CB38.1 CB39.1 CT21.1 CT36.1 CT42.1 CT52.1 CT62.1 CT70.1 CT89.1 CT119.1 RB27.2 RB29.1 RB30.1 RB31.1 RB47.1 RB48.1 RB49.1 UB2.5(V+) UB3.3(~{CLR}) UB3.8(VCC) UB4.3(~{CLR}) UB4.8(VCC) UB5.3(~{CLR}) UB5.8(VCC) UB6.5(V+) UB7.5(V+) UB8.5(V+) UB9.3(~{CLR}) UB9.8(VCC) UB10.3(~{CLR}) UB10.8(VCC) UB11.3(~{CLR}) UB11.8(VCC) UB12.5(V+) UB13.5(V+) UB14.5(V+) UT3.5(V+) UT10.5(V+) UT11.5(V+) UT14.5(V+) UT16.3(EN) UT16.4(VIN) UT18.5(V+) UT21.5(V+) UT32.5(V+) ; also on sheet 1 2 4 5 6 7 8 9 10 11
0: CB8.2 CB9.1 CB10.1 CB11.2 CB12.2 CB13.2 CB14.2 CB18.1 CB19.1 CB20.1 CB21.2 CB22.2 CB23.2 CB27.2 CB28.2 CB29.2 CB33.1 CB34.1 CB35.1 CB37.2 CB38.2 CB39.2 CB48.2 CB49.2 CB50.2 CB51.2 CB52.2 CB53.2 CB61.2 CB62.2 CB63.2 CB64.2 CB65.2 CB66.2 CB67.2 CT15.1 CT21.2 CT34.1 CT36.2 CT39.1 CT42.2 CT47.1 CT52.2 CT58.2 CT59.2 CT62.2 CT65.1 CT70.2 CT81.1 CT89.2 CT112.1 CT119.2 RB28.1 RT27.1 UB2.2(V-) UB3.1(~{A}) UB3.4(GND) UB4.1(~{A}) UB4.4(GND) UB5.1(~{A}) UB5.4(GND) UB6.2(V-) UB7.2(V-) UB8.2(V-) UB9.1(~{A}) UB9.4(GND) UB10.1(~{A}) UB10.4(GND) UB11.1(~{A}) UB11.4(GND) UB12.2(V-) UB13.2(V-) UB14.2(V-) UT3.2(V-) UT10.2(V-) UT11.2(V-) UT14.2(V-) UT16.2(GND) UT18.2(V-) UT21.2(V-) UT32.2(V-) ; also on sheet 1 2 3 4 5 6 7 8 9 10 11
CASE-TEMP: CB11.1 RB26.2 ; also on sheet 5
U-RTD: RB32.1 UB3.2(B) ; also on sheet 5 8
U-TEMP: CB48.1 RB66.2 ; also on sheet 5
V-RTD: RB33.1 UB4.2(B) ; also on sheet 5 8
V-TEMP: CB49.1 RB67.2 ; also on sheet 5
V_U+: JT43.12 RT55.1
V_U-: JT43.11 RB19.1
V_V+: JT43.10 RT67.1
V_V-: JT43.9 RB41.1
V_W+: JT43.8 RT84.1
V_W-: JT43.7 RB59.1
V_X+: JT43.6 RT106.1
V_X-: JT43.5 RB74.1
V_Y+: JT43.4 RT130.1
V_Y-: JT43.3 RB83.1
V_Z+: JT43.2 RT174.1
V_Z-: JT43.1 RB103.1
VDC-M: JT1.2 RT37.1
VDC-P: JT1.1 RT7.1
Vsense-DC: CB61.1 RB65.2 ; also on sheet 3 5
Vsense-U: CB62.1 RB72.2 ; also on sheet 3 5
Vsense-V: CB63.1 RB73.2 ; also on sheet 3 5
Vsense-W: CB64.1 RB80.2 ; also on sheet 3 5
Vsense-X: CB65.1 RB81.2 ; also on sheet 3 5
Vsense-Y: CB66.1 RB82.2 ; also on sheet 3 5
Vsense-Z: CB67.1 RB89.2 ; also on sheet 3 5
W-RTD: RB34.1 UB5.2(B) ; also on sheet 5 8
W-TEMP: CB50.1 RB68.2 ; also on sheet 5
X-RTD: RB50.1 UB9.2(B) ; also on sheet 5 9
X-TEMP: CB51.1 RB69.2 ; also on sheet 5
Y-RTD: RB51.1 UB10.2(B) ; also on sheet 5 9
Y-TEMP: CB52.1 RB70.2 ; also on sheet 5
Z-RTD: RB52.1 UB11.2(B) ; also on sheet 5 9
Z-TEMP: CB53.1 RB71.2 ; also on sheet 5
N16187: CB24.2 RB66.1 UB6.1(OUT) UB6.4(IN-)
N16636: CB24.1 RB35.2 RB38.1
N16643: CB18.2 RB38.2 UB6.3(IN+)
N18013: CB25.1 RB36.2 RB39.1
N18021: CB25.2 RB67.1 UB7.1(OUT) UB7.4(IN-)
N18093: CB19.2 RB39.2 UB7.3(IN+)
N18488: CB26.1 RB37.2 RB40.1
N18496: CB26.2 RB68.1 UB8.1(OUT) UB8.4(IN-)
N18568: CB20.2 RB40.2 UB8.3(IN+)
N76078: CT15.2 RT12.2 RT27.2 RT29.1
N76134: RT29.2 UT3.3(IN+)
N76224: CT17.2 RB65.1 RT36.2 UT3.1(OUT)
N76236: RT43.2 UT3.4(IN-)
N76260: CT17.1 RT36.1 RT42.2 RT43.1
N78650: CB7.1 RB18.1 RB25.2
N78658: CB7.2 RB26.1 UB2.1(OUT) UB2.4(IN-)
N78724: CB9.2 RB18.2 UB2.3(IN+)
N79088: CB10.2 RB25.1 RB27.1 RB28.2
N139937: RT10.2 RT11.1
N139941: RT11.2 RT12.1
N140053: RT40.2 RT41.1
N140057: RT41.2 RT42.1
N273504: RB32.2 RB35.1 UB3.5(Q)
N273798: CB15.2 UB3.6(CEXT)
N273802: CB15.1 RB29.2 UB3.7(REXT/CEXT)
N275299: RB33.2 RB36.1 UB4.5(Q)
N275399: CB16.1 RB30.2 UB4.7(REXT/CEXT)
N275407: CB16.2 UB4.6(CEXT)
N275841: RB34.2 RB37.1 UB5.5(Q)
N275941: CB17.1 RB31.2 UB5.7(REXT/CEXT)
N275949: CB17.2 UB5.6(CEXT)
N368949: RB50.2 RB53.1 UB9.5(Q)
N368957: CB40.1 RB53.2 RB56.1
N368965: CB40.2 RB69.1 UB12.1(OUT) UB12.4(IN-)
N369195: CB33.2 RB56.2 UB12.3(IN+)
N369283: CB30.1 RB47.2 UB9.7(REXT/CEXT)
N369291: CB30.2 UB9.6(CEXT)
N369511: CB41.1 RB54.2 RB57.1
N369519: CB41.2 RB70.1 UB13.1(OUT) UB13.4(IN-)
N369535: RB51.2 RB54.1 UB10.5(Q)
N369765: CB34.2 RB57.2 UB13.3(IN+)
N369853: CB31.1 RB48.2 UB10.7(REXT/CEXT)
N369861: CB31.2 UB10.6(CEXT)
N370089: RB52.2 RB55.1 UB11.5(Q)
N370097: CB42.1 RB55.2 RB58.1
N370105: CB42.2 RB71.1 UB14.1(OUT) UB14.4(IN-)
N370335: CB35.2 RB58.2 UB14.3(IN+)
N370423: CB32.1 RB49.2 UB11.7(REXT/CEXT)
N370431: CB32.2 UB11.6(CEXT)
N4927414: RB21.2 RB22.1
N4927416: RB22.2 RB23.1
N4927418: RB23.2 RB24.1
N4927420: RT57.2 RT58.1
N4927422: RT58.2 RT59.1
N4927424: RT59.2 RT60.1
N4927426: CT34.2 RT60.2 RT61.2 RT62.1
N4927452: RT69.2 RT70.1
N4927454: RT70.2 RT71.1
N4927456: RT71.2 RT72.1
N4927458: CT39.2 RT72.2 RT73.2 RT74.1
N4927466: RB43.2 RB44.1
N4927468: RB44.2 RB45.1
N4927470: RB45.2 RB46.1
N4927472: CT41.1 RB46.2 RT76.1 RT77.1
N4927476: RT86.2 RT87.1
N4927478: RT87.2 RT88.1
N4927480: RT88.2 RT89.1
N4927482: CT47.2 RT89.2 RT90.2 RT92.1
N4927490: RB61.2 RB62.1
N4927492: RB62.2 RB63.1
N4927494: RB63.2 RB64.1
N4927496: CT50.1 RB64.2 RT94.1 RT97.1
N4927508: RT55.2 RT56.1
N4927510: RB19.2 RB20.1
N4927512: RT56.2 RT57.1
N4927514: RB20.2 RB21.1
N4927522: RT67.2 RT68.1
N4927524: RT68.2 RT69.1
N4927528: RB41.2 RB42.1
N4927530: RB42.2 RB43.1
N4927534: RT84.2 RT85.1
N4927536: RT85.2 RT86.1
N4927540: RB59.2 RB60.1
N4927542: RB60.2 RB61.1
N4927556: CT35.2 RB72.1 RT64.2 UT10.1(OUT)
N4927564: CT35.1 RB24.2 RT64.1 RT65.1
N4927568: RT65.2 UT10.4(IN-)
N4927572: RT62.2 UT10.3(IN+)
N4927618: RT74.2 UT11.3(IN+)
N4927622: CT41.2 RB73.1 RT76.2 UT11.1(OUT)
N4927628: RT77.2 UT11.4(IN-)
N4927670: RT92.2 UT14.3(IN+)
N4927674: CT50.2 RB80.1 RT94.2 UT14.1(OUT)
N4927680: RT97.2 UT14.4(IN-)
N4932848: RB76.2 RB77.1
N4932850: RB77.2 RB78.1
N4932852: RB78.2 RB79.1
N4932854: RT108.2 RT109.1
N4932856: RT109.2 RT110.1
N4932858: RT110.2 RT111.1
N4932860: CT65.2 RT111.2 RT112.2 RT114.1
N4932886: RT132.2 RT133.1
N4932888: RT133.2 RT134.1
N4932890: RT134.2 RT135.1
N4932892: CT81.2 RT135.2 RT136.2 RT137.1
N4932900: RB85.2 RB86.1
N4932902: RB86.2 RB87.1
N4932904: RB87.2 RB88.1
N4932906: CT86.1 RB88.2 RT141.1 RT142.1
N4932910: RT176.2 RT177.1
N4932912: RT177.2 RT178.1
N4932914: RT178.2 RT179.1
N4932916: CT112.2 RT173.2 RT179.2 RT180.1
N4932924: RB105.2 RB106.1
N4932926: RB106.2 RB107.1
N4932928: RB107.2 RB108.1
N4932930: CT117.1 RB108.2 RT184.1 RT191.1
N4932934: RT106.2 RT107.1
N4932936: RB74.2 RB75.1
N4932938: RT107.2 RT108.1
N4932940: RB75.2 RB76.1
N4932948: RT130.2 RT131.1
N4932950: RT131.2 RT132.1
N4932954: RB83.2 RB84.1
N4932956: RB84.2 RB85.1
N4932960: RT174.2 RT175.1
N4932962: RT175.2 RT176.1
N4932966: RB103.2 RB104.1
N4932968: RB104.2 RB105.1
N4932978: CT68.2 RB81.1 RT116.2 UT18.1(OUT)
N4932986: CT68.1 RB79.2 RT116.1 RT118.1
N4932990: RT118.2 UT18.4(IN-)
N4932994: RT114.2 UT18.3(IN+)
N4933040: RT137.2 UT21.3(IN+)
N4933044: CT86.2 RB82.1 RT141.2 UT21.1(OUT)
N4933050: RT142.2 UT21.4(IN-)
N4933092: RT180.2 UT32.3(IN+)
N4933096: CT117.2 RB89.1 RT184.2 UT32.1(OUT)
N4933102: RT191.2 UT32.4(IN-)
N5087389: RT7.2 RT8.1
N5087393: RT8.2 RT9.1
N5087445: RT37.2 RT38.1
N5087449: RT38.2 RT39.1
N5087463: RT9.2 RT10.1
N5087477: RT39.2 RT40.1
N5226863: CT59.1 UT16.5(VREF)

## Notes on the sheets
sheet 13
- UVW
- XYZ
- Board
- fc = 1002 Hz
  Q = 0.7048
sheet 14
- 300V max, 2/5 W, 0.1%
- HV Differential
- VEXT Fc = 6.5 kHz
- 1.5V Bias for Voltage Sensors UVW, XYZ, DC
sheet 15
- HV DC BUS
- 300V max, 2/5 W, 0.1%
- VDC Fc = 6.5 kHz
sheet 16
- 300V max, 2/5 W, 0.1%
- VEXT Fc = 6.5 kHz
